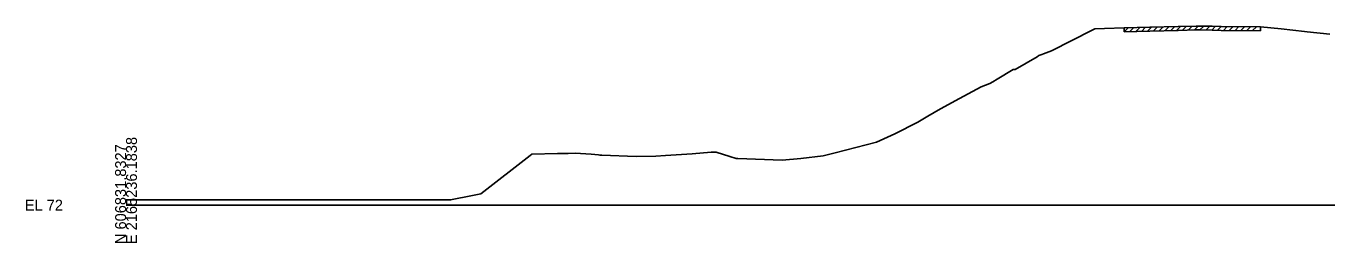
# Model space of a CAD drawing. Extents: x -26 to 6803, y -10 to 19606.
# Drawn here: x 3974.3 to 4308.5, y 17490.3 to 17545.9 of the extents above; entities that cross this region are included whole.
import ezdxf

# ---------------------------------------------------------------- set-up
doc = ezdxf.new("R2010")
doc.units = 0
for name, color, linetype in [('RD_GPK_XS_Cell', 7, 'Continuous'), ('RD_XS_ExGround', 7, 'Continuous'), ('RD_XS_ExPaveRet', 7, 'Continuous')]:
    doc.layers.add(name, color=color, linetype=linetype)

msp = doc.modelspace()

# ---------------------------------------------------------------- linework, layer by layer
at = {"layer": 'RD_GPK_XS_Cell'}
msp.add_line((4000, 17500), (4400, 17500), dxfattribs=at)
at = {"layer": 'RD_XS_ExGround'}
msp.add_lwpolyline([(4000, 17501.34), (4048.86, 17501.34), (4083.34, 17501.34), (4088.95, 17502.45), (4091.1, 17502.88), (4103.84, 17512.75), (4104.27, 17513.1), (4110.85, 17513.25), (4113.54, 17513.22), (4115.32, 17513.29), (4119.45, 17513.02), (4121.39, 17512.89), (4121.73, 17512.84), (4122.24, 17512.81), (4131.06, 17512.5), (4136.04, 17512.57), (4138.54, 17512.7), (4145.42, 17513.17), (4150.25, 17513.57), (4151.59, 17513.58), (4155.07, 17512.48), (4156.72, 17511.97), (4157.12, 17511.95), (4168.5, 17511.5), (4173.33, 17511.97), (4179.09, 17512.65), (4182.12, 17513.38), (4192.79, 17516.16), (4197.44, 17518.28), (4203.35, 17521.3), (4203.76, 17521.52), (4205.94, 17522.83), (4209.17, 17524.72), (4214.1, 17527.37), (4219.68, 17530.34), (4221.9, 17531.21), (4222.6, 17531.63), (4223.75, 17532.26), (4227.83, 17534.76), (4228.39, 17534.79), (4234.02, 17538.03), (4234.49, 17538.36), (4235.2, 17538.63), (4235.68, 17538.78), (4237.68, 17539.53), (4248.12, 17544.86), (4248.8, 17545.2), (4251.33, 17545.25), (4256.35, 17545.44), (4262.93, 17545.6), (4270.21, 17545.78), (4274.84, 17545.9), (4275.17, 17545.9), (4275.84, 17545.9), (4278.99, 17545.86), (4281.28, 17545.79), (4291.37, 17545.72), (4296.7, 17545.2), (4302.66, 17544.5), (4303.34, 17544.4), (4309.2, 17543.79)], dxfattribs=at)
at = {"layer": 'RD_XS_ExPaveRet'}
for p, q in [((4256.35, 17544.44), (4257.37, 17545.47)), ((4256.35, 17544.44), (4256.35, 17545.44)), ((4256.35, 17544.44), (4262.93, 17544.6)), ((4257.85, 17544.48), (4258.87, 17545.5)), ((4259.35, 17544.51), (4260.37, 17545.54)), ((4260.85, 17544.55), (4261.87, 17545.58)), ((4262.35, 17544.59), (4263.37, 17545.62)), ((4262.93, 17544.6), (4270.21, 17544.78)), ((4263.85, 17544.63), (4264.87, 17545.65)), ((4265.35, 17544.66), (4266.37, 17545.69)), ((4266.85, 17544.7), (4267.87, 17545.72)), ((4268.35, 17544.74), (4269.37, 17545.76)), ((4269.85, 17544.77), (4270.87, 17545.8)), ((4270.21, 17544.78), (4274.84, 17544.9)), ((4271.35, 17544.81), (4272.37, 17545.84)), ((4272.85, 17544.85), (4273.87, 17545.87)), ((4274.35, 17544.89), (4275.36, 17545.9)), ((4274.84, 17544.9), (4275.17, 17544.9)), ((4275.17, 17544.9), (4275.84, 17544.9)), ((4275.84, 17544.9), (4278.99, 17544.86)), ((4275.85, 17544.9), (4276.84, 17545.89)), ((4277.35, 17544.88), (4278.34, 17545.87)), ((4278.85, 17544.86), (4279.82, 17545.84)), ((4278.99, 17544.86), (4281.28, 17544.79)), ((4280.35, 17544.82), (4281.32, 17545.79)), ((4281.28, 17544.79), (4291.37, 17544.72)), ((4281.85, 17544.79), (4282.84, 17545.78)), ((4283.35, 17544.78), (4284.34, 17545.77)), ((4284.85, 17544.77), (4285.84, 17545.76)), ((4286.35, 17544.76), (4287.34, 17545.75)), ((4287.85, 17544.74), (4288.84, 17545.74)), ((4289.35, 17544.73), (4290.34, 17545.73)), ((4291.37, 17545.72), (4291.37, 17544.72)), ((4291.37, 17544.72), (4291.37, 17544.72))]:
    msp.add_line(p, q, dxfattribs=at)

# ---------------------------------------------------------------- texts
at = {"layer": 'RD_GPK_XS_Cell'}
for s, p in [('E 2165236.1838', (4002.8, 17490)), ('N 606831.8327', (4000, 17490))]:
    msp.add_text(s, height=2.8, rotation=90, dxfattribs=at).set_placement(p)
msp.add_text('EL 72', height=2.8, dxfattribs=at).set_placement((3974, 17498.6))

doc.saveas('drawing.dxf')
